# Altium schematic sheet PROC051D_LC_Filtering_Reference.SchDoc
size 431 x 279 mm; Date: Not shown in title block; ApprovedBy: Not shown in title block; CheckedBy: Not shown in title block; Author: Not shown in title block; CompanyName: Not shown in title block; Engineer: Not shown in title block; Organization: Not shown in title block; Address1: Not shown in title block; Address2: Not shown in title block; Address3: Not shown in title block; Address4: Not shown in title block; DocumentNumber: 5; Revision: Use project parameter SCH_Rev; SheetNumber: 5; SheetTotal: 16; PageSetup: Record=PageOptions¦CenterHorizontal=True¦CenterVertical=True¦PrintScale=1.00¦XCorrection=1.00¦YCorrection=1.00¦PrintKind=0¦BorderSize=5000000¦LeftOffset=0¦BottomOffset=0¦Orientation=2¦PaperLength=1000¦PaperWidth=1000¦Scale=100¦PaperSource=15¦PrintQuality=600¦MediaType=1¦DitherType=10¦PaperKind=Letter¦PrintScaleMode=1
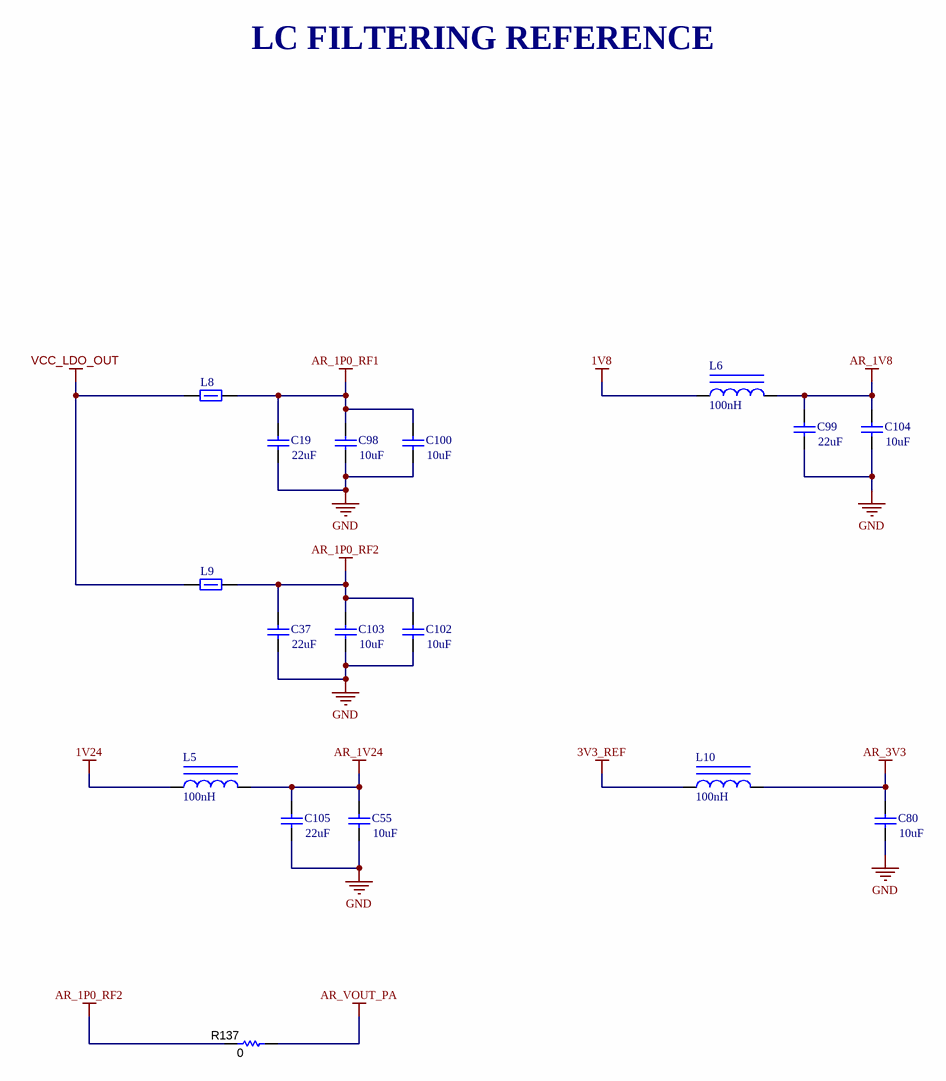
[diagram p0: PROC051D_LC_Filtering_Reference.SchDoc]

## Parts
C19  ValueDisplayed: 22uF  [1206_180]  (hidden comment: CGA5L1X7R0J226M160AC)
C37  ValueDisplayed: 22uF  [1206_180]  (hidden comment: CGA5L1X7R0J226M160AC)
C55  ValueDisplayed: 10uF  [0805_HV]  (hidden comment: GCM21BR71A106KE22L)
C80  ValueDisplayed: 10uF  [0805_HV]  (hidden comment: GCM21BR71A106KE22L)
C98  ValueDisplayed: 10uF  [0805_HV]  (hidden comment: GCM21BR71A106KE22L)
C99  ValueDisplayed: 22uF  [1206_180]  (hidden comment: CGA5L1X7R0J226M160AC)
C100  ValueDisplayed: 10uF  [0805_HV]  (hidden comment: GCM21BR71A106KE22L)
C102  ValueDisplayed: 10uF  [0805_HV]  (hidden comment: GCM21BR71A106KE22L)
C103  ValueDisplayed: 10uF  [0805_HV]  (hidden comment: GCM21BR71A106KE22L)
C104  ValueDisplayed: 10uF  [0805_HV]  (hidden comment: GCM21BR71A106KE22L)
C105  ValueDisplayed: 22uF  [1206_180]  (hidden comment: CGA5L1X7R0J226M160AC)
L5  ValueDisplayed: 100nH  [NLCV32]  (hidden comment: NLCV32T-R10M-EFRD)
L6  ValueDisplayed: 100nH  [NLCV32]  (hidden comment: NLCV32T-R10M-EFRD)
L8  BLM18KG121TH1D  [0603]  (value not drawn)
L9  BLM18KG121TH1D  [0603]  (value not drawn)
L10  ValueDisplayed: 100nH  [NLCV32]  (hidden comment: NLCV32T-R10M-EFRD)
R137  ValueDisplayed: 0  [0603]  (hidden comment: MCT06030Z0000ZP500)

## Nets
1V8: L6.1
1V24: L5.1
3V3_REF: L10.1
AR_1P0_RF1: C19.1 C98.1 C100.1 L8.2
AR_1P0_RF2: C37.1 C102.1 C103.1 L9.2 R137.1
AR_1V8: C99.1 C104.1 L6.2
AR_1V24: C55.1 C105.1 L5.2
AR_3V3: C80.1 L10.2
AR_VOUT_PA: R137.2
GND: C19.2 C37.2 C55.2 C80.2 C98.2 C99.2 C100.2 C102.2 C103.2 C104.2 C105.2
VCC_LDO_OUT: L8.1 L9.1

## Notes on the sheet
- LC FILTERING REFERENCE

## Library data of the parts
C19 C37 C99 C105 = CMP-0008770-2: CAP, CERM, 22 uF, 6.3 V, +/- 10%, X7R, AEC-Q200 Grade 1, 1206; Manufacturer: TDK; TaMin_C: -55°C; ESR_ohm: 1.872m; Polarized: N; SizeAreaWB_mm2: 10.92; Value1: 0.001872 ohm; U/M: EA; Value: 22uF; SizeZ_mm: 1.8; SizeX_mm: 3.2; SizeY_mm: 1.6; Value2: 6.3V; SizeArea_mm2: 5.12; AEC Qualified: Y; Cap_F: 22µF; IRMS_A: 5.30203A; AEC Grade: 1; AEC Category: Q200; TaMax_C: 125°C
C55 C80 C98 C100 C102-C104 = CMP-0008017-2: CAP, CERM, 10 uF, 10 V, +/- 10%, X7R, 0805; Manufacturer: MuRata; TaMin_C: -55°C; Polarized: N; SizeAreaWB_mm2: 6.75; Value1: Unknown; U/M: EA; Value: 10uF; TaMax_C: 125°C; SizeZ_mm: 1.45; SizeX_mm: 2; SizeY_mm: 1.25; Cap_Case: 0805; Value2: 10V; SizeArea_mm2: 2.5; Cap_F: 10µF; AEC Category: Q200
L5 L6 L10 = CMP-0083745-1: Inductor, Wirewound, Ferrite, 100 nH, 2.85 A, 0.024 ohm, AEC-Q200 Grade 1, SMD; Manufacturer: TDK; Isat: 2.85A @ 10% inductance drop; Irms: 2.85A @ 40C rise; SizeAreaWB_mm2: 13.44; DCR_ohm: 0.024; Value: 100nH; Imax_A: 2.85A; SizeZ_mm: 2.5; SizeX_mm: 3.2; SizeY_mm: 2.2; SizeArea_mm2: 7.04; AEC Qualified: Y; AEC Grade: 1; AEC Category: Q200
L8 L9 = CMP-0077879-2: Ferrite Bead, 120 ohm @ 100 MHz, 1.9 A, 0603; Manufacturer: MuRata; ZTyp@100MHz_Ohm: 120; SizeAreaWB_mm2: 4.68; DCR_ohm: 0.04; Value1: 0.04 ohm; Value: 120 ohm; Imax_A: 1.9A; SizeZ_mm: 1.0; SizeX_mm: 1.6; SizeY_mm: 0.8; SizeArea_mm2: 1.28
R137 = CMP-0025884-3: RES, 0, 5%, 0.125 W, 0603; Manufacturer: Vishay/Beyschlag; Power_W: 125mW; TempCo: ppm/C; Value_Code: 0000; U/M: EA; Value: 0; EIA_Code: E24; SizeX_mm: 1.6; SizeY_mm: 0.8; SizeZ_mm: 1; Value2: 0.125W; SizeArea_mm2: 1.28; CompType: Resistor; AEC Qualified: N; AEC Category: Q200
